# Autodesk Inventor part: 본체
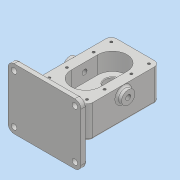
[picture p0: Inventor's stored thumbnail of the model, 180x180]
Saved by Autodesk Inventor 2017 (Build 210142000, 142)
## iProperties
Part Number: 본체
Material: 일반
Document SubType Name: Modeling
Designer: MRC
Density: 1 g/cm^3
Appearance: 기본값
Author: MRC
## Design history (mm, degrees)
sketch "스케치1"
  geometry: L1 (40, -60)-(-40, -60); L2 (-40, -60)-(-40, 60); L3 (-40, 60)-(40, 60); L4 (40, 60)-(40, -60); L5 (40, -60)-(-40, 60); L6 (-40, -60)-(40, 60); 1 further point
  constraints: 12 end point, 2 midpoint, 2 parallel, 1 horizontal, 1 perpendicular
  dimensions: "d0" = 80 distance of L2.end L3.end; "d1" = 120 distance of L1.end L2.end
extrude "돌출1" new body sketch "스케치1" distance "d2" = 14; taper "d4" = 0 deg; dims "d3" = 39, "d5" = 0
sketch "스케치2"
  geometry: L1 (0, 22)-(0, -22); L2 (-24, 22)-(-24, -22); L3 (24, -22)-(24, 22); A1 r 24 centre (0, 22) between (24, 22) and (-24, 22); A2 r 24 centre (0, -22) between (-24, -22) and (24, -22); 2 further points
  constraints: 8 end point, 4 point on circle, 4 tangent, 2 centre point, 2 coincident, 1 midpoint, 1 parallel, 1 vertical
  dimensions: "d6" = 24 radius of A1; "d7" = 92 dimension on A1 A2
extrude "돌출2" cut sketch "스케치2" distance "d8" = 29; taper "d9" = 0 deg
sketch "스케치3"
  geometry: C1 r 12.5 at (0, 22); C2 r 12.5 at (0, -22); A1 r 24 centre (0, -22) between (-24, -22) and (24, -22) reference; A2 r 24 centre (0, 22) between (24, 22) and (-24, 22) reference; 1 further point
  constraints: 2 centre point, 2 coincident
  dimensions: "d10" = 25 diameter of C1; "d11" = 25 diameter of C2
extrude "돌출3" cut sketch "스케치3" distance "d12" = 15; taper "d13" = 0 deg
sketch "스케치4"
  geometry: C1 r 19 at (0, 22); C2 r 12.5 at (0, 22) reference; 1 further point
  constraints: 1 centre point, 1 concentric
  dimensions: "d14" = 38 diameter of C1
extrude "돌출4" join sketch "스케치4" distance "d15" = 17; taper "d16" = 0 deg
hole "구멍1" diameter "d19" = 17; stored, may be unused: countersink angle "d23" = 90 deg, drill point angle "d25" = 118 deg; dims "d17" = 10, "d18" = 10, "d20" = 6, "d21" = 28, "d22" = 7.3, "d24" = 8
sketch "스케치5"
  geometry: L1 (40, -60)-(40, 60) reference; L2 (-31, 51)-(31, 51); L3 (31, 51)-(31, 22); L4 (31, 22)-(31, -22); L5 (31, -22)-(31, -51); L6 (31, -51)-(-31, -51); L7 (-31, -51)-(-31, -22); L8 (-31, -22)-(-31, 22); L9 (-31, 22)-(-31, 51); A1 r 24 centre (0, 22) between (24, 22) and (-24, 22) reference; 3 further points
  constraints: 16 end point, 3 perpendicular, 3 vertical alignment, 2 midpoint, 2 parallel, 1 collinear, 1 horizontal alignment, 1 vertical
  dimensions: "d26" = 102 distance of L6.end L2.start; "d27" = 44 distance of L7.end L8.end; "d28" = 29 distance of L2.start L8.end; "d99" = 29 distance of L2.end L3.end; "d100" = 44 distance of L3.end L4.end; "d101" = 62 distance of L2.end L2.start
hole "구멍2" sketch "스케치5" at (-31, 51), (-31, 22), (-31, -22), (-31, -51), (31, -51), (31, -22), (31, 22), (31, 51) diameter "d29" = 4.134; stored, may be unused: countersink angle "d33" = 90 deg, drill point angle "d35" = 118 deg; dims "d30" = 10, "d31" = 28, "d32" = 7.3, "d34" = 12
sketch "스케치6"
  geometry: C1 r 11 at (14, 60); 1 further point
  constraints: 1 centre point, 1 coincident
  dimensions: "d36" = 22 diameter of C1
extrude "돌출5" join sketch "스케치6" distance "d37" = 8; taper "d38" = 0 deg
hole "구멍3" diameter "d41" = 8.376; stored, may be unused: countersink angle "d45" = 90 deg, drill point angle "d47" = 118 deg; dims "d42" = 20, "d43" = 28, "d44" = 7.3, "d46" = 27.3, "d96" = 10, "d97" = 10
node "작업 평면1"
sketch "스케치7"
  geometry: L1 (-60, 44)-(60, 44); L2 (60, 44)-(60, -56); L3 (60, -56)-(-60, -56); L4 (-60, -56)-(-60, 44); L5 (-60, 44)-(60, -56); L6 (60, 44)-(-60, -56); L7 (-19, -56)-(19, -56) reference; 3 further points
  constraints: 12 end point, 4 midpoint, 2 parallel, 1 horizontal, 1 perpendicular, 1 vertical alignment
  dimensions: "d51" = 120 distance of L2.end L3.end; "d52" = 100 distance of L1.end L2.end
extrude "돌출6" join sketch "스케치7" distance "d53" = 10; taper "d54" = 0 deg
sketch "스케치8"
  geometry: L1 (-65.05, -30.369)-(-80, -39); L2 (-62.591, 3.949)-(-80, 14); L3 (-80, -56)-(-80, 44) reference; L4 (-90, -56)-(-80, -56) reference; L5 (-80, 44)-(-80, -56) reference; 1 further point
  constraints: 4 end point, 2 point on line
  dimensions: "d56" = 60 deg angle of L2 L3; "d57" = 17 distance from line of L4 L1.end; "d58" = 60 deg angle of L3 L1; "d59" = 53 distance of L1.end L2.end
feature "리브1" dims "d60" = 1, "d61" = 48, "d62" = 0, "d63" = 0, "d64" = 1, "d65" = 1
feature "리브2" dims "d66" = 1, "d67" = 48, "d68" = 0, "d69" = 0, "d70" = 1, "d71" = 1
fillet "모깎기1" dims "d72" = 10
sketch "스케치9"
  geometry: C1 r 4.5 at (-50, 46); A1 r 10 centre (-50, 46) between (-50, 56) and (-60, 46) reference; 1 further point
  constraints: 1 centre point, 1 coincident
  dimensions: "d73" = 9 diameter of C1
extrude "돌출7" cut sketch "스케치9" distance "d74" = 10; taper "d75" = 0 deg
fillet "모깎기2" dims "d82" = 9
fillet "모깎기3" dims "d83" = 3
fillet "모깎기4" dims "d84" = 3
chamfer "모따기1" distance "d85" = 1; stored, may be unused: second distance "d86" = 2, angle "d87" = 45 deg
chamfer "모따기2" distance "d88" = 0.7; stored, may be unused: second distance "d89" = 2, angle "d90" = 30 deg
sketch "스케치10"
  geometry: L1 (-50, -44)-(50, -44) reference; L2 (60, -34)-(60, 46) reference; 2 further points
  constraints: 1 other
  dimensions: "d92" = 10 distance from line of L1 point (0, -34); "d93" = 60 distance from line of L2 point (0, -34)
feature "엠보싱1" sketch "스케치10" dims "d0" = 80, "d1" = 120, "d94" = 0.5, "d95" = 0
fillet "모깎기5" dims "d98" = 0.5
chamfer "모따기3" distance "d102" = 1; stored, may be unused: second distance "d103" = 2, angle "d104" = 30 deg
node "솔리드1"
mirror "미러1"
pattern_linear "직사각형 패턴1" dims "d78" = 80, "d81" = 100
